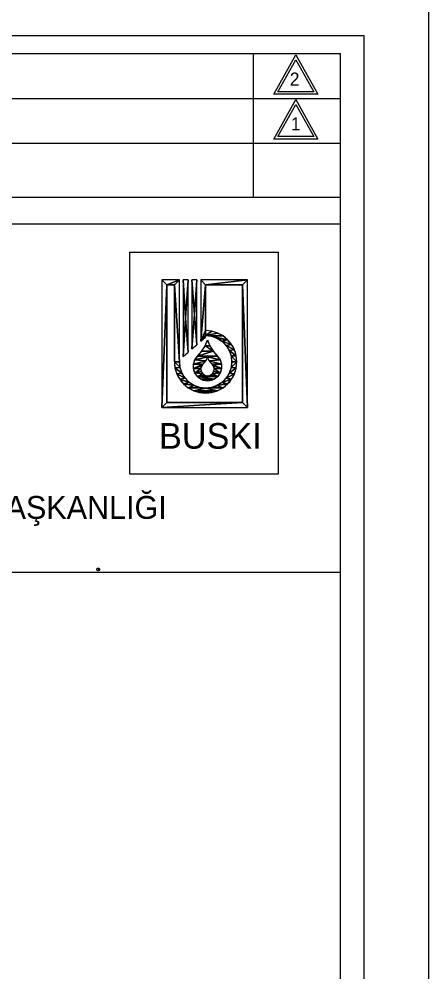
# Model space of a CAD drawing. Extents: x -17 to 1145, y -10 to 821.
# Drawn here: x 1082.1 to 1145, y 143.5 to 289.5 of the extents above; entities that cross this region are included whole.
import ezdxf

# ---------------------------------------------------------------- set-up
doc = ezdxf.new("R2010")
doc.units = 0
for name, color, linetype in [('Level 1', 7, 'Continuous'), ('Level 20', 7, 'Continuous'), ('Level 21', 7, 'Continuous'), ('Level 51', 7, 'Continuous'), ('Level 6', 7, 'Continuous'), ('Level 7', 7, 'Continuous'), ('Level 8', 7, 'Continuous')]:
    doc.layers.add(name, color=color, linetype=linetype)

msp = doc.modelspace()

# ---------------------------------------------------------------- linework, layer by layer
at = {"layer": 'Level 1'}
for p, q in [((960, 287), (1135, 287)), ((1135, 287), (1135, 0))]:
    msp.add_line(p, q, dxfattribs=at)
msp.add_lwpolyline([(1094.31, 205.37), (1094.35, 205.37), (1094.43, 205.33), (1094.48, 205.24), (1094.48, 205.07), (1094.39, 204.99), (1094.26, 204.94), (1094.14, 204.99), (1094.05, 205.07), (1094.05, 205.24), (1094.09, 205.33), (1094.18, 205.37), (1094.31, 205.37), (1094.43, 205.24), (1094.43, 205.11), (1094.35, 205.03), (1094.26, 204.94), (1094.35, 205.07), (1094.35, 205.28), (1094.31, 205.37)], dxfattribs=at)
msp.add_lwpolyline([(1094.31, 205.37), (1094.35, 205.37), (1094.43, 205.33), (1094.48, 205.24), (1094.48, 205.07), (1094.39, 204.99), (1094.26, 204.94), (1094.14, 204.99), (1094.05, 205.07), (1094.05, 205.24), (1094.09, 205.33), (1094.18, 205.37), (1094.31, 205.37), (1094.43, 205.24), (1094.43, 205.11), (1094.35, 205.03), (1094.26, 204.94), (1094.35, 205.07), (1094.35, 205.28), (1094.31, 205.37)], dxfattribs=at)
msp.add_lwpolyline([(1094.31, 205.37), (1094.35, 205.37), (1094.43, 205.33), (1094.48, 205.24), (1094.48, 205.07), (1094.39, 204.99), (1094.26, 204.94), (1094.14, 204.99), (1094.05, 205.07), (1094.05, 205.24), (1094.09, 205.33), (1094.18, 205.37), (1094.31, 205.37), (1094.43, 205.24), (1094.43, 205.11), (1094.35, 205.03), (1094.26, 204.94), (1094.35, 205.07), (1094.35, 205.28), (1094.31, 205.37)], dxfattribs=at)
msp.add_lwpolyline([(1094.31, 205.37), (1094.35, 205.37), (1094.43, 205.33), (1094.48, 205.24), (1094.48, 205.07), (1094.39, 204.99), (1094.26, 204.94), (1094.14, 204.99), (1094.05, 205.07), (1094.05, 205.24), (1094.09, 205.33), (1094.18, 205.37), (1094.31, 205.37), (1094.43, 205.24), (1094.43, 205.11), (1094.35, 205.03), (1094.26, 204.94), (1094.35, 205.07), (1094.35, 205.28), (1094.31, 205.37)], dxfattribs=at)
at = {"layer": 'Level 51'}
msp.add_lwpolyline([(-17, -10), (1145, -10), (1145, 821), (-17, 821)], close=True, dxfattribs=at)
at = {"layer": 'Level 6'}
for p, q in [((963.47, 284.22), (1131.45, 284.22)), ((963.47, 284.22), (1131.45, 284.22)), ((963.47, 284.22), (1131.45, 284.22)), ((963.47, 284.22), (1131.45, 284.22)), ((966.6, 284.22), (1128.32, 284.22)), ((966.6, 284.22), (1128.32, 284.22)), ((966.6, 284.22), (1128.32, 284.22)), ((966.6, 284.22), (1128.32, 284.22)), ((966.6, 284.22), (1128.32, 284.22)), ((966.6, 284.22), (1128.32, 284.22)), ((966.6, 284.22), (1128.32, 284.22)), ((966.6, 284.22), (1128.32, 284.22)), ((1118.07, 262.2), (1118.07, 284.22)), ((1118.07, 262.2), (1118.07, 284.22)), ((1118.07, 262.2), (1118.07, 284.22)), ((1118.07, 262.2), (1118.07, 284.22)), ((1131.45, 260.69), (1131.45, 284.22)), ((1131.45, 260.69), (1131.45, 284.22)), ((1131.45, 260.69), (1131.45, 284.22)), ((1131.45, 260.69), (1131.45, 284.22)), ((1131.45, 260.69), (1131.45, 284.22)), ((1131.45, 260.69), (1131.45, 284.22)), ((1131.45, 260.69), (1131.45, 284.22)), ((1131.45, 260.69), (1131.45, 284.22)), ((963.47, 277.35), (1131.45, 277.35)), ((963.47, 277.35), (1131.45, 277.35)), ((963.47, 277.35), (1131.45, 277.35)), ((963.47, 277.35), (1131.45, 277.35)), ((963.47, 270.49), (1131.45, 270.49)), ((963.47, 270.49), (1131.45, 270.49)), ((963.47, 270.49), (1131.45, 270.49)), ((963.47, 270.49), (1131.45, 270.49)), ((1131.45, 4.97), (1131.45, 267.9)), ((1131.45, 4.97), (1131.45, 267.9)), ((1131.45, 4.97), (1131.45, 267.9)), ((1131.45, 4.97), (1131.45, 267.9)), ((963.47, 262.2), (1131.45, 262.2)), ((963.47, 262.2), (1131.45, 262.2)), ((963.47, 262.2), (1131.45, 262.2)), ((963.47, 262.2), (1131.45, 262.2)), ((963.47, 258.11), (1131.45, 258.11)), ((963.47, 258.11), (1131.45, 258.11)), ((963.47, 258.11), (1131.45, 258.11)), ((963.47, 258.11), (1131.45, 258.11)), ((963.47, 204.75), (1131.45, 204.75)), ((963.47, 204.75), (1131.45, 204.75)), ((963.47, 204.75), (1131.45, 204.75)), ((963.47, 204.75), (1131.45, 204.75))]:
    msp.add_line(p, q, dxfattribs=at)
at = {"layer": 'Level 7'}
for points in [[(1121.21, 277.97), (1124.58, 284.02), (1127.95, 277.97)], [(1121.21, 277.97), (1124.58, 284.02), (1127.95, 277.97)], [(1121.21, 277.97), (1124.58, 284.02), (1127.95, 277.97)], [(1121.21, 277.97), (1124.58, 284.02), (1127.95, 277.97)], [(1121.83, 278.34), (1124.58, 283.27), (1127.33, 278.34)], [(1121.83, 278.34), (1124.58, 283.27), (1127.33, 278.34)], [(1121.83, 278.34), (1124.58, 283.27), (1127.33, 278.34)], [(1121.83, 278.34), (1124.58, 283.27), (1127.33, 278.34)], [(1121.21, 271.11), (1124.58, 277.16), (1127.95, 271.11)], [(1121.21, 271.11), (1124.58, 277.16), (1127.95, 271.11)], [(1121.21, 271.11), (1124.58, 277.16), (1127.95, 271.11)], [(1121.21, 271.11), (1124.58, 277.16), (1127.95, 271.11)], [(1121.83, 271.48), (1124.58, 276.41), (1127.33, 271.48)], [(1121.83, 271.48), (1124.58, 276.41), (1127.33, 271.48)], [(1121.83, 271.48), (1124.58, 276.41), (1127.33, 271.48)], [(1121.83, 271.48), (1124.58, 276.41), (1127.33, 271.48)]]:
    msp.add_lwpolyline(points, close=True, dxfattribs=at)
at = {"layer": 'Level 8'}
for points in [[(1099.09, 253.77), (1121.88, 253.77), (1121.88, 219.76), (1099.09, 219.76)], [(1104.03, 249.52), (1104.03, 229.97), (1104.79, 248.76)], [(1104.79, 248.76), (1106.71, 249.52), (1104.03, 249.52)], [(1104.03, 249.52), (1104.03, 229.97), (1104.79, 248.76)], [(1104.79, 248.76), (1106.71, 249.52), (1104.03, 249.52)], [(1104.79, 248.76), (1104.03, 229.97), (1104.79, 230.73)], [(1104.79, 248.76), (1104.03, 229.97), (1104.79, 230.73)], [(1106.71, 249.52), (1104.79, 248.76), (1105.95, 248.76)], [(1106.71, 249.52), (1104.79, 248.76), (1105.95, 248.76)], [(1106.71, 249.52), (1105.95, 248.76), (1106.71, 236.97)], [(1106.71, 249.52), (1105.95, 248.76), (1106.71, 236.97)], [(1105.95, 248.76), (1105.95, 236.97), (1106.71, 236.97)], [(1105.95, 248.76), (1105.95, 236.97), (1106.71, 236.97)], [(1107.67, 243.65), (1108.05, 249.52), (1107.29, 249.52)], [(1107.67, 243.65), (1107.29, 249.52), (1107.29, 237.79)], [(1107.67, 243.65), (1108.05, 249.52), (1107.29, 249.52)], [(1107.67, 243.65), (1107.29, 249.52), (1107.29, 237.79)], [(1107.67, 243.65), (1108.05, 238.43), (1108.05, 249.52)], [(1107.67, 243.65), (1108.05, 238.43), (1108.05, 249.52)], [(1109.02, 244.24), (1109.4, 249.52), (1108.64, 249.52)], [(1109.02, 244.24), (1108.64, 249.52), (1108.64, 238.96)], [(1109.02, 244.24), (1109.4, 249.52), (1108.64, 249.52)], [(1109.02, 244.24), (1108.64, 249.52), (1108.64, 238.96)], [(1109.02, 244.24), (1109.4, 239.6), (1109.4, 249.52)], [(1109.02, 244.24), (1109.4, 239.6), (1109.4, 249.52)], [(1109.98, 249.52), (1109.98, 240.12), (1110.74, 248.76)], [(1110.74, 248.76), (1117.15, 249.52), (1109.98, 249.52)], [(1109.98, 249.52), (1109.98, 240.12), (1110.74, 248.76)], [(1110.74, 248.76), (1117.15, 249.52), (1109.98, 249.52)], [(1110.74, 248.76), (1109.98, 240.12), (1110.74, 241.76)], [(1110.74, 248.76), (1109.98, 240.12), (1110.74, 241.76)], [(1117.15, 249.52), (1110.74, 248.76), (1116.4, 248.76)], [(1117.15, 249.52), (1110.74, 248.76), (1116.4, 248.76)], [(1117.15, 249.52), (1116.4, 248.76), (1117.15, 229.97)], [(1117.15, 249.52), (1116.4, 248.76), (1117.15, 229.97)], [(1116.4, 248.76), (1116.4, 230.73), (1117.15, 229.97)], [(1116.4, 248.76), (1116.4, 230.73), (1117.15, 229.97)], [(1109.02, 244.24), (1108.64, 238.96), (1109.4, 239.6)], [(1109.02, 244.24), (1108.64, 238.96), (1109.4, 239.6)], [(1107.67, 243.65), (1107.29, 237.79), (1108.05, 238.43)], [(1107.67, 243.65), (1107.29, 237.79), (1108.05, 238.43)], [(1110.74, 241.76), (1109.98, 240.12), (1110.74, 241)], [(1110.74, 241.76), (1109.98, 240.12), (1110.74, 241)], [(1110.74, 241), (1109.98, 240.12), (1110.74, 240.77)], [(1110.74, 241), (1109.98, 240.12), (1110.74, 240.77)], [(1110.74, 241.76), (1110.74, 241), (1111.67, 241.66)], [(1110.74, 241.76), (1110.74, 241), (1111.67, 241.66)], [(1111.67, 241.66), (1110.74, 241), (1112.57, 241.39)], [(1111.67, 241.66), (1110.74, 241), (1112.57, 241.39)], [(1112.57, 241.39), (1110.74, 241), (1113.39, 240.95)], [(1112.57, 241.39), (1110.74, 241), (1113.39, 240.95)], [(1110.74, 241), (1111.63, 240.9), (1113.39, 240.95)], [(1110.74, 241), (1111.63, 240.9), (1113.39, 240.95)], [(1113.39, 240.95), (1111.63, 240.9), (1114.12, 240.36)], [(1113.39, 240.95), (1111.63, 240.9), (1114.12, 240.36)], [(1111.03, 240.36), (1111.39, 239.44), (1110.67, 239.44)], [(1111.03, 240.36), (1111.39, 239.44), (1110.67, 239.44)], [(1111.63, 240.9), (1112.48, 240.6), (1114.12, 240.36)], [(1111.63, 240.9), (1112.48, 240.6), (1114.12, 240.36)], [(1112.48, 240.6), (1113.25, 240.12), (1114.12, 240.36)], [(1112.48, 240.6), (1113.25, 240.12), (1114.12, 240.36)], [(1114.12, 240.36), (1113.25, 240.12), (1114.71, 239.63)], [(1114.12, 240.36), (1113.25, 240.12), (1114.71, 239.63)], [(1113.25, 240.12), (1113.88, 239.48), (1114.71, 239.63)], [(1113.25, 240.12), (1113.88, 239.48), (1114.71, 239.63)], [(1114.71, 239.63), (1113.88, 239.48), (1115.16, 238.8)], [(1114.71, 239.63), (1113.88, 239.48), (1115.16, 238.8)], [(1113.88, 239.48), (1114.36, 238.72), (1115.16, 238.8)], [(1113.88, 239.48), (1114.36, 238.72), (1115.16, 238.8)], [(1111.9, 238.6), (1112.55, 237.85), (1109.51, 237.85)], [(1110.16, 238.6), (1111.9, 238.6), (1109.51, 237.85)], [(1111.9, 238.6), (1112.55, 237.85), (1109.51, 237.85)], [(1110.16, 238.6), (1111.9, 238.6), (1109.51, 237.85)], [(1110.67, 239.44), (1111.9, 238.6), (1110.16, 238.6)], [(1110.67, 239.44), (1111.9, 238.6), (1110.16, 238.6)], [(1111.39, 239.44), (1111.9, 238.6), (1110.67, 239.44)], [(1111.39, 239.44), (1111.9, 238.6), (1110.67, 239.44)], [(1115.16, 238.8), (1114.36, 238.72), (1115.43, 237.91)], [(1115.16, 238.8), (1114.36, 238.72), (1115.43, 237.91)], [(1114.36, 238.72), (1114.66, 237.87), (1115.43, 237.91)], [(1114.36, 238.72), (1114.66, 237.87), (1115.43, 237.91)], [(1105.95, 236.97), (1106.04, 236.04), (1106.81, 236.08)], [(1106.71, 236.97), (1105.95, 236.97), (1106.81, 236.08)], [(1105.95, 236.97), (1106.04, 236.04), (1106.81, 236.08)], [(1106.71, 236.97), (1105.95, 236.97), (1106.81, 236.08)], [(1108.87, 236.64), (1110.33, 236.62), (1108.86, 235.95)], [(1108.87, 236.64), (1110.33, 236.62), (1108.86, 235.95)], [(1110.33, 236.62), (1110.09, 236.29), (1108.86, 235.95)], [(1110.33, 236.62), (1110.09, 236.29), (1108.86, 235.95)], [(1109.1, 237.3), (1110.76, 237.13), (1108.87, 236.64)], [(1109.1, 237.3), (1110.76, 237.13), (1108.87, 236.64)], [(1110.76, 237.13), (1110.33, 236.62), (1108.87, 236.64)], [(1110.76, 237.13), (1110.33, 236.62), (1108.87, 236.64)], [(1109.51, 237.85), (1111.03, 237.73), (1109.1, 237.3)], [(1109.51, 237.85), (1111.03, 237.73), (1109.1, 237.3)], [(1111.03, 237.73), (1110.76, 237.13), (1109.1, 237.3)], [(1111.03, 237.73), (1110.76, 237.13), (1109.1, 237.3)], [(1112.55, 237.85), (1111.03, 237.73), (1109.51, 237.85)], [(1112.55, 237.85), (1111.03, 237.73), (1109.51, 237.85)], [(1112.55, 237.85), (1112.96, 237.3), (1111.03, 237.73)], [(1112.55, 237.85), (1112.96, 237.3), (1111.03, 237.73)], [(1111.03, 237.73), (1112.96, 237.3), (1111.3, 237.13)], [(1111.03, 237.73), (1112.96, 237.3), (1111.3, 237.13)], [(1112.96, 237.3), (1113.18, 236.64), (1111.3, 237.13)], [(1112.96, 237.3), (1113.18, 236.64), (1111.3, 237.13)], [(1111.3, 237.13), (1113.18, 236.64), (1111.73, 236.62)], [(1111.3, 237.13), (1113.18, 236.64), (1111.73, 236.62)], [(1113.18, 236.64), (1113.19, 235.95), (1111.73, 236.62)], [(1113.18, 236.64), (1113.19, 235.95), (1111.73, 236.62)], [(1111.73, 236.62), (1113.19, 235.95), (1111.97, 236.29)], [(1111.73, 236.62), (1113.19, 235.95), (1111.97, 236.29)], [(1115.43, 237.91), (1114.66, 237.87), (1115.52, 236.97)], [(1115.43, 237.91), (1114.66, 237.87), (1115.52, 236.97)], [(1114.66, 237.87), (1114.76, 236.97), (1115.52, 236.97)], [(1114.66, 237.87), (1114.76, 236.97), (1115.52, 236.97)], [(1115.52, 236.97), (1114.66, 236.08), (1115.43, 236.04)], [(1114.76, 236.97), (1114.66, 236.08), (1115.52, 236.97)], [(1115.52, 236.97), (1114.66, 236.08), (1115.43, 236.04)], [(1114.76, 236.97), (1114.66, 236.08), (1115.52, 236.97)], [(1106.81, 236.08), (1106.04, 236.04), (1107.11, 235.23)], [(1106.81, 236.08), (1106.04, 236.04), (1107.11, 235.23)], [(1106.04, 236.04), (1106.32, 235.14), (1107.11, 235.23)], [(1106.04, 236.04), (1106.32, 235.14), (1107.11, 235.23)], [(1107.11, 235.23), (1106.32, 235.14), (1107.59, 234.46)], [(1107.11, 235.23), (1106.32, 235.14), (1107.59, 234.46)], [(1106.32, 235.14), (1106.76, 234.32), (1107.59, 234.46)], [(1106.32, 235.14), (1106.76, 234.32), (1107.59, 234.46)], [(1110.09, 236.29), (1110, 235.89), (1108.86, 235.95)], [(1110.09, 236.29), (1110, 235.89), (1108.86, 235.95)], [(1108.86, 235.95), (1110, 235.89), (1109.07, 235.3)], [(1108.86, 235.95), (1110, 235.89), (1109.07, 235.3)], [(1110, 235.89), (1110.07, 235.49), (1109.07, 235.3)], [(1110, 235.89), (1110.07, 235.49), (1109.07, 235.3)], [(1110.07, 235.49), (1110.29, 235.14), (1109.07, 235.3)], [(1110.07, 235.49), (1110.29, 235.14), (1109.07, 235.3)], [(1109.07, 235.3), (1110.29, 235.14), (1109.47, 234.74)], [(1109.07, 235.3), (1110.29, 235.14), (1109.47, 234.74)], [(1110.29, 235.14), (1110.63, 234.91), (1109.47, 234.74)], [(1110.29, 235.14), (1110.63, 234.91), (1109.47, 234.74)], [(1111.77, 235.14), (1112.59, 234.74), (1111.43, 234.91)], [(1111.77, 235.14), (1112.59, 234.74), (1111.43, 234.91)], [(1111.99, 235.49), (1112.99, 235.3), (1111.77, 235.14)], [(1111.99, 235.49), (1112.99, 235.3), (1111.77, 235.14)], [(1112.99, 235.3), (1112.59, 234.74), (1111.77, 235.14)], [(1112.99, 235.3), (1112.59, 234.74), (1111.77, 235.14)], [(1111.97, 236.29), (1113.19, 235.95), (1112.06, 235.89)], [(1111.97, 236.29), (1113.19, 235.95), (1112.06, 235.89)], [(1112.06, 235.89), (1112.99, 235.3), (1111.99, 235.49)], [(1112.06, 235.89), (1112.99, 235.3), (1111.99, 235.49)], [(1113.19, 235.95), (1112.99, 235.3), (1112.06, 235.89)], [(1113.19, 235.95), (1112.99, 235.3), (1112.06, 235.89)], [(1114.36, 235.23), (1113.88, 234.46), (1115.16, 235.14)], [(1114.36, 235.23), (1113.88, 234.46), (1115.16, 235.14)], [(1115.16, 235.14), (1113.88, 234.46), (1114.71, 234.32)], [(1115.16, 235.14), (1113.88, 234.46), (1114.71, 234.32)], [(1114.66, 236.08), (1114.36, 235.23), (1115.43, 236.04)], [(1114.66, 236.08), (1114.36, 235.23), (1115.43, 236.04)], [(1115.43, 236.04), (1114.36, 235.23), (1115.16, 235.14)], [(1115.43, 236.04), (1114.36, 235.23), (1115.16, 235.14)], [(1107.59, 234.46), (1106.76, 234.32), (1108.23, 233.83)], [(1107.59, 234.46), (1106.76, 234.32), (1108.23, 233.83)], [(1106.76, 234.32), (1107.36, 233.59), (1108.23, 233.83)], [(1106.76, 234.32), (1107.36, 233.59), (1108.23, 233.83)], [(1108.23, 233.83), (1107.36, 233.59), (1108.99, 233.35)], [(1108.23, 233.83), (1107.36, 233.59), (1108.99, 233.35)], [(1110.63, 234.91), (1111.03, 234.83), (1109.47, 234.74)], [(1110.63, 234.91), (1111.03, 234.83), (1109.47, 234.74)], [(1111.03, 234.83), (1112.59, 234.74), (1109.47, 234.74)], [(1111.03, 234.83), (1112.59, 234.74), (1109.47, 234.74)], [(1109.47, 234.74), (1112.03, 234.33), (1110.03, 234.33)], [(1112.59, 234.74), (1112.03, 234.33), (1109.47, 234.74)], [(1109.47, 234.74), (1112.03, 234.33), (1110.03, 234.33)], [(1112.59, 234.74), (1112.03, 234.33), (1109.47, 234.74)], [(1110.03, 234.33), (1111.37, 234.11), (1110.68, 234.11)], [(1112.03, 234.33), (1111.37, 234.11), (1110.03, 234.33)], [(1110.03, 234.33), (1111.37, 234.11), (1110.68, 234.11)], [(1112.03, 234.33), (1111.37, 234.11), (1110.03, 234.33)], [(1111.43, 234.91), (1112.59, 234.74), (1111.03, 234.83)], [(1111.43, 234.91), (1112.59, 234.74), (1111.03, 234.83)], [(1113.25, 233.83), (1112.48, 233.35), (1114.12, 233.59)], [(1113.25, 233.83), (1112.48, 233.35), (1114.12, 233.59)], [(1113.88, 234.46), (1113.25, 233.83), (1114.71, 234.32)], [(1113.88, 234.46), (1113.25, 233.83), (1114.71, 234.32)], [(1114.71, 234.32), (1113.25, 233.83), (1114.12, 233.59)], [(1114.71, 234.32), (1113.25, 233.83), (1114.12, 233.59)], [(1107.36, 233.59), (1108.08, 232.99), (1108.99, 233.35)], [(1107.36, 233.59), (1108.08, 232.99), (1108.99, 233.35)], [(1108.99, 233.35), (1108.08, 232.99), (1109.84, 233.05)], [(1108.99, 233.35), (1108.08, 232.99), (1109.84, 233.05)], [(1109.84, 233.05), (1108.08, 232.99), (1110.74, 232.95)], [(1109.84, 233.05), (1108.08, 232.99), (1110.74, 232.95)], [(1108.08, 232.99), (1108.91, 232.55), (1110.74, 232.95)], [(1108.08, 232.99), (1108.91, 232.55), (1110.74, 232.95)], [(1110.74, 232.95), (1108.91, 232.55), (1112.57, 232.55)], [(1110.74, 232.95), (1108.91, 232.55), (1112.57, 232.55)], [(1108.91, 232.55), (1109.8, 232.28), (1111.67, 232.28)], [(1112.57, 232.55), (1108.91, 232.55), (1111.67, 232.28)], [(1108.91, 232.55), (1109.8, 232.28), (1111.67, 232.28)], [(1112.57, 232.55), (1108.91, 232.55), (1111.67, 232.28)], [(1111.67, 232.28), (1109.8, 232.28), (1110.74, 232.19)], [(1111.67, 232.28), (1109.8, 232.28), (1110.74, 232.19)], [(1111.63, 233.05), (1110.74, 232.95), (1113.39, 232.99)], [(1111.63, 233.05), (1110.74, 232.95), (1113.39, 232.99)], [(1113.39, 232.99), (1110.74, 232.95), (1112.57, 232.55)], [(1113.39, 232.99), (1110.74, 232.95), (1112.57, 232.55)], [(1112.48, 233.35), (1111.63, 233.05), (1113.39, 232.99)], [(1112.48, 233.35), (1111.63, 233.05), (1113.39, 232.99)], [(1114.12, 233.59), (1112.48, 233.35), (1113.39, 232.99)], [(1114.12, 233.59), (1112.48, 233.35), (1113.39, 232.99)], [(1116.4, 230.73), (1104.03, 229.97), (1117.15, 229.97)], [(1104.03, 229.97), (1116.4, 230.73), (1104.79, 230.73)], [(1116.4, 230.73), (1104.03, 229.97), (1117.15, 229.97)], [(1104.03, 229.97), (1116.4, 230.73), (1104.79, 230.73)]]:
    msp.add_lwpolyline(points, close=True, dxfattribs=at)
for points in [[(1106.71, 236.97), (1106.71, 236.97), (1106.71, 249.52), (1104.03, 249.52), (1104.03, 229.97), (1117.15, 229.97), (1117.15, 249.52), (1109.98, 249.52), (1109.98, 240.12), (1110.74, 240.77), (1110.74, 241)], [(1106.71, 236.97), (1106.71, 236.97), (1106.71, 249.52), (1104.03, 249.52), (1104.03, 229.97), (1117.15, 229.97), (1117.15, 249.52), (1109.98, 249.52), (1109.98, 240.12), (1110.74, 240.77), (1110.74, 241)], [(1105.95, 236.97), (1105.95, 236.97), (1105.95, 248.76), (1104.79, 248.76), (1104.79, 230.73), (1116.4, 230.73), (1116.4, 248.76), (1110.74, 248.76), (1110.74, 241.76)], [(1105.95, 236.97), (1105.95, 236.97), (1105.95, 248.76), (1104.79, 248.76), (1104.79, 230.73), (1116.4, 230.73), (1116.4, 248.76), (1110.74, 248.76), (1110.74, 241.76)], [(1108.05, 249.52), (1107.29, 249.52), (1107.29, 237.79), (1108.05, 238.43), (1108.05, 249.52)], [(1108.05, 249.52), (1107.29, 249.52), (1107.29, 237.79), (1108.05, 238.43), (1108.05, 249.52)], [(1108.64, 238.96), (1109.4, 239.6), (1109.4, 249.52), (1108.64, 249.52), (1108.64, 238.96)], [(1108.64, 238.96), (1109.4, 239.6), (1109.4, 249.52), (1108.64, 249.52), (1108.64, 238.96)], [(1110.74, 241.76), (1110.74, 241.76)], [(1110.74, 241.76), (1110.74, 241.76)], [(1110.74, 241), (1110.74, 241)], [(1110.74, 241), (1110.74, 241)]]:
    msp.add_lwpolyline(points, dxfattribs=at)
for centre, radius, start, end in [((1110.74, 236.97), 4.78, 180, 90), ((1110.74, 236.97), 4.78, 180, 90), ((1110.74, 236.97), 4.03, 180, 90), ((1110.74, 236.97), 4.03, 180, 90), ((1105.44, 242.02), 5.83, 314.2894, 343.392), ((1105.44, 242.02), 5.83, 314.2894, 343.392), ((1116.62, 242.02), 5.83, 196.608, 225.7106), ((1116.62, 242.02), 5.83, 196.608, 225.7106), ((1111.03, 236.27), 2.19, 133.9191, 46.0809), ((1111.03, 236.27), 2.19, 133.9191, 46.0809), ((1111.03, 235.86), 1.03, 132.7094, 47.2906), ((1111.03, 235.86), 1.03, 132.7094, 47.2906), ((1108.78, 238.37), 2.33, 311.4103, 344.0384), ((1108.78, 238.37), 2.33, 311.4103, 344.0384), ((1113.27, 238.37), 2.33, 195.9616, 228.5897), ((1113.27, 238.37), 2.33, 195.9616, 228.5897)]:
    msp.add_arc(centre, radius, start, end, dxfattribs=at)

# ---------------------------------------------------------------- texts
at = {"layer": 'Level 1'}
for s, p in [('2', (1123.65, 279.3)), ('1', (1123.82, 272.43))]:
    msp.add_text(s, height=2, dxfattribs=at).set_placement(p)
at = {"layer": 'Level 20'}
msp.add_text('PLANLAMA YATIRIM VE İNŞAAT DAİRE BAŞKANLIĞI', height=3.5, dxfattribs=at).set_placement((989.03, 212.91))
at = {"layer": 'Level 21'}
msp.add_text('BUSKI', height=3.926, dxfattribs=at).set_placement((1103.59, 223.66))
msp.add_text('BUSKI', height=3.926, dxfattribs=at).set_placement((1103.59, 223.66))

doc.saveas('drawing.dxf')
